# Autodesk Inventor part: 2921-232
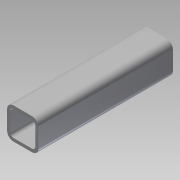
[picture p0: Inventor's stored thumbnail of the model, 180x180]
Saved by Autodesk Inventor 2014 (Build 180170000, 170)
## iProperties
Company: NHTSA/VRTC
Created: 2012-08
Part Number: 2921-232
Material: Steel, Mild
Document SubType Name: Modeling
Designer: Mike Vanvoorhis
Density: 7.86 g/cm^3
Mass: 262.006 g
Surface Area: 318.54 cm^2
Volume: 33.3341 cm^3
Project: CHILD SIDE IMPACT SLED
Description: HONEYCOMB FRAME EXTENSION TUBE
Stock Number: T.S. 1 1/4" x 1 1/4" x 1/8" x 0'-5 3/8" (136.5 mm)
Appearance: Steel
Author: Dave Walker
Title: Honeycomb Frame Extension Tube
Subject: Child Side Impact Sled
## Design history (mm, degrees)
sketch "Sketch1"
  geometry: L1 (6.35, 0)-(25.4, 0); L2 (31.75, 6.35)-(31.75, 25.4); L3 (25.4, 31.75)-(6.35, 31.75); L4 (0, 25.4)-(0, 6.35); L5 (6.35, 28.575)-(25.4, 28.575); L6 (28.575, 25.4)-(28.575, 6.35); L7 (25.4, 3.175)-(6.35, 3.175); L8 (3.175, 6.35)-(3.175, 25.4); A1 r 6.35 centre (6.35, 25.4) between (6.35, 31.75) and (0, 25.4); A2 r 6.35 centre (25.4, 25.4) between (31.75, 25.4) and (25.4, 31.75); A3 r 6.35 centre (25.4, 6.35) between (25.4, 0) and (31.75, 6.35); A4 r 6.35 centre (6.35, 6.35) between (0, 6.35) and (6.35, 0); A5 r 3.175 centre (25.4, 25.4) between (28.575, 25.4) and (25.4, 28.575); A6 r 3.175 centre (25.4, 6.35) between (25.4, 3.175) and (28.575, 6.35); A7 r 3.175 centre (6.35, 6.35) between (3.175, 6.35) and (6.35, 3.175); A8 r 3.175 centre (6.35, 25.4) between (6.35, 28.575) and (3.175, 25.4); A9 r 3.175 centre (6.35, 25.4) between (6.35, 28.575) and (3.175, 25.4); A10 r 3.175 centre (6.35, 6.35) between (3.175, 6.35) and (6.35, 3.175); A11 r 3.175 centre (25.4, 6.35) between (25.4, 3.175) and (28.575, 6.35); A12 r 3.175 centre (25.4, 25.4) between (28.575, 25.4) and (25.4, 28.575); 4 further points
  constraints: 24 point on circle, 16 end point, 16 point on line, 16 tangent, 12 centre point, 6 equal radius, 4 parallel, 2 perpendicular, 1 horizontal, 7 other
  dimensions: "d0" = 31.75 distance of point (0, 31.75) point (31.75, 31.75); "d1" = 31.75 distance of point (31.75, 31.75) point (31.75, 0); "d2" = 6.35 radius of A1; "d5" = 3.175 distance between parallel lines of L8 L4; "d6" = 3.175 radius of A9
extrude "Extrusion1" new body sketch "Sketch1" distance "d3" = 136.525; taper "d4" = 0 deg
body "Solid1"
